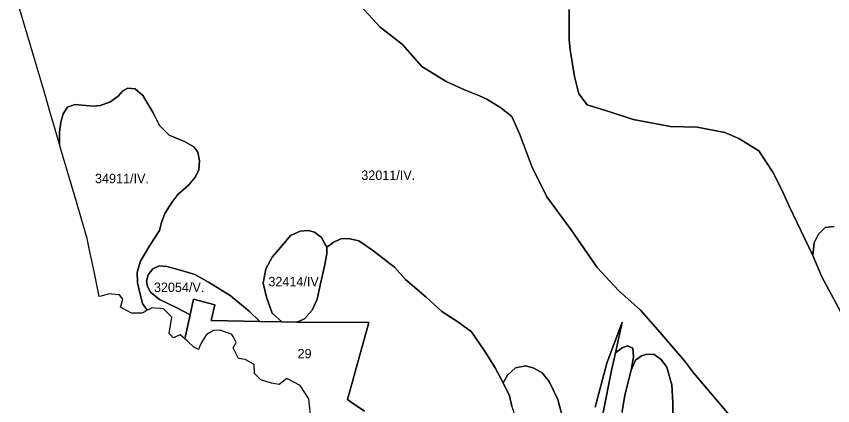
# Model space of a CAD drawing. Extents: x -521621 to -516761, y -1190184 to -1184927.
# Drawn here: x -521384 to -520083, y -1188713 to -1188092 of the extents above; entities that cross this region are included whole.
import ezdxf

# ---------------------------------------------------------------- set-up
doc = ezdxf.new("R2010")
doc.units = 0
doc.layers.add('BPEJ_s', color=7, linetype='Continuous')

msp = doc.modelspace()

# ---------------------------------------------------------------- linework, layer by layer
at = {"layer": 'BPEJ_s'}
for p, q in [((-520502.9, -1188129.6), (-520502.9, -1188081.1)), ((-520501.2, -1188145.7), (-520502.9, -1188129.6)), ((-520494.4, -1188188), (-520501.2, -1188145.7)), ((-520487.6, -1188215.9), (-520494.4, -1188188)), ((-520474, -1188233.3), (-520487.6, -1188215.9)), ((-520437.7, -1188244.7), (-520474, -1188233.3)), ((-520400.7, -1188256.8), (-520437.7, -1188244.7)), ((-520341.1, -1188268.1), (-520400.7, -1188256.8)), ((-520298.8, -1188268.9), (-520341.1, -1188268.1)), ((-520254.9, -1188277.2), (-520298.8, -1188268.9)), ((-520232.3, -1188287), (-520254.9, -1188277.2)), ((-520200.6, -1188306.6), (-520232.3, -1188287)), ((-520177.9, -1188340.7), (-520200.6, -1188306.6)), ((-520163.5, -1188370.1), (-520177.9, -1188340.7)), ((-520152.2, -1188395.1), (-520163.5, -1188370.1)), ((-520114.5, -1188473.7), (-520152.2, -1188395.1)), ((-520094.8, -1188429.1), (-520105.4, -1188439.7)), ((-520080.5, -1188427.6), (-520094.8, -1188429.1)), ((-520105.4, -1188439.7), (-520112.2, -1188453.3)), ((-520112.2, -1188453.3), (-520114.5, -1188473.7))]:
    msp.add_line(p, q, dxfattribs=at)
for points in [[(-520515.5, -1188723.6), (-520520.8, -1188703.3), (-520534.6, -1188674.4), (-520545.6, -1188660.6), (-520559, -1188653.2), (-520572, -1188649.6), (-520588.3, -1188652.8), (-520600.9, -1188664.6), (-520607.8, -1188676.4), (-520620.8, -1188652.8), (-520637.5, -1188625.6), (-520658.6, -1188595.1), (-520680.2, -1188579.6), (-520687.6, -1188574.8), (-520706, -1188563.1), (-520730.7, -1188540.2), (-520763.4, -1188512.1), (-520781.3, -1188492.3), (-520816.1, -1188464.9), (-520837.8, -1188450.3), (-520854.7, -1188446.4), (-520866.8, -1188447.2), (-520879, -1188452.6), (-520889.3, -1188460.5), (-520892.4, -1188454.9), (-520897.7, -1188444.9), (-520908.7, -1188436.4), (-520918.2, -1188433.6), (-520931.8, -1188434.6), (-520946.9, -1188441.8), (-520959.9, -1188457.2), (-520976.3, -1188476.1), (-520986.2, -1188494.7), (-520990.4, -1188517.8), (-520985.3, -1188540.2), (-520976, -1188565.5), (-520960.7, -1188579.6), (-520995.8, -1188578.9), (-521012.8, -1188562.3), (-521043.2, -1188537.6), (-521077.7, -1188516.2), (-521099.2, -1188504), (-521120.9, -1188497.3), (-521144, -1188490.9), (-521156.4, -1188490.2), (-521166.4, -1188495), (-521173.7, -1188504.3), (-521176.3, -1188514.6), (-521174.7, -1188522.9), (-521169.9, -1188532.2), (-521155.5, -1188544), (-521128.3, -1188557.1), (-521106.9, -1188568.1), (-521115.5, -1188606.2), (-521122.8, -1188600.2), (-521130.1, -1188603.1), (-521134.1, -1188604.8), (-521138.4, -1188599.9), (-521140.1, -1188597.9), (-521136, -1188571.9), (-521140.8, -1188567.2), (-521147.2, -1188560.8), (-521149.4, -1188558.5), (-521154.4, -1188558.1), (-521163.3, -1188557.4), (-521168, -1188557), (-521171.5, -1188558.9), (-521175.3, -1188561), (-521182.8, -1188549.9), (-521186.7, -1188535.5), (-521191, -1188517.3), (-521191.5, -1188500), (-521186.2, -1188482.7), (-521170.8, -1188456.7), (-521155.9, -1188433.6), (-521152.6, -1188420.7), (-521147.3, -1188406.7), (-521136.2, -1188388.9), (-521126.6, -1188376.4), (-521108.8, -1188361.1), (-521098.3, -1188348.1), (-521093, -1188337), (-521092, -1188322.6), (-521094.9, -1188308.7), (-521101.2, -1188300.5), (-521116, -1188291.8), (-521123.7, -1188288.5), (-521140.1, -1188281.7), (-521155.9, -1188266.4), (-521166.5, -1188245.2), (-521182.3, -1188218.3), (-521194.8, -1188207.7), (-521206.4, -1188206.8), (-521214, -1188211.1), (-521221.7, -1188219.7), (-521234.7, -1188228.9), (-521250.1, -1188234.2), (-521261.1, -1188235.6), (-521273.1, -1188234.6), (-521290.9, -1188232.7), (-521302.4, -1188237), (-521309.1, -1188247.6), (-521313, -1188261.1), (-521315.4, -1188276.9), (-521314.9, -1188296.7), (-521317.1, -1188289.2), (-521322.5, -1188270.7), (-521329.3, -1188247.6), (-521339.3, -1188213.6), (-521384, -1188061.2)], [(-520247.4, -1188728.4), (-520304.4, -1188660.6), (-520318.7, -1188641.4), (-520361.4, -1188592.2), (-520389, -1188560.5), (-520424, -1188529.5), (-520458.1, -1188492.5), (-520499.7, -1188432.9), (-520538.2, -1188380), (-520562.4, -1188331.6), (-520581.3, -1188280.9), (-520594.1, -1188252.2), (-520611.5, -1188237.9), (-520634.1, -1188224.3), (-520645.5, -1188219.2), (-520669.4, -1188209.2), (-520698.6, -1188195.9), (-520737.7, -1188172), (-520768.2, -1188136.9), (-520804, -1188109.7), (-520834.6, -1188075.8)], [(-520834.6, -1188075.8), (-520804, -1188109.7), (-520768.2, -1188136.9), (-520737.7, -1188172), (-520698.6, -1188195.9), (-520669.4, -1188209.2), (-520645.5, -1188219.2), (-520634.1, -1188224.3), (-520611.5, -1188237.9), (-520594.1, -1188252.2), (-520581.3, -1188280.9), (-520562.4, -1188331.6), (-520538.2, -1188380), (-520499.7, -1188432.9), (-520458.1, -1188492.5), (-520424, -1188529.5), (-520389, -1188560.5), (-520361.4, -1188592.2), (-520318.7, -1188641.4), (-520304.4, -1188660.6), (-520247.4, -1188728.4)], [(-520502.9, -1188081.1), (-520502.9, -1188105), (-520502.9, -1188129.6), (-520501.2, -1188145.7), (-520494.4, -1188188), (-520487.6, -1188215.9), (-520474, -1188233.3), (-520437.7, -1188244.7), (-520400.7, -1188256.8), (-520341.1, -1188268.1), (-520298.8, -1188268.9), (-520254.9, -1188277.2), (-520232.3, -1188287), (-520200.6, -1188306.6), (-520177.9, -1188340.7), (-520163.5, -1188370.1), (-520152.2, -1188395.1), (-520114.5, -1188473.7), (-520100.1, -1188507.7), (-520062.3, -1188578)], [(-520062.3, -1188578), (-520100.1, -1188507.7), (-520114.5, -1188473.7), (-520112.2, -1188453.3), (-520105.4, -1188439.7), (-520094.8, -1188429.1), (-520080.5, -1188427.6)], [(-520829.1, -1188721.8), (-520850.2, -1188707.6), (-520855.9, -1188703.2), (-520822, -1188580.5), (-520936.8, -1188579.8), (-520924.5, -1188574.4), (-520912.6, -1188561), (-520904.3, -1188543.1), (-520899.8, -1188521), (-520892.6, -1188490.7), (-520889.3, -1188470.8), (-520889.3, -1188460.5), (-520879, -1188452.6), (-520866.8, -1188447.2), (-520854.7, -1188446.4), (-520837.8, -1188450.3), (-520816.1, -1188464.9), (-520781.3, -1188492.3), (-520763.4, -1188512.1), (-520730.7, -1188540.2), (-520706, -1188563.1), (-520687.6, -1188574.8), (-520680.2, -1188579.6), (-520658.6, -1188595.1), (-520637.5, -1188625.6), (-520620.8, -1188652.8), (-520607.8, -1188676.4), (-520598, -1188697.6), (-520594, -1188713.9)], [(-520914.1, -1188738.4), (-520917.9, -1188702.1), (-520931.6, -1188681.1), (-520952.7, -1188669.8), (-520964.8, -1188679.1), (-520977.1, -1188677.4), (-520994.2, -1188671.8), (-521004.3, -1188661.6), (-521004.7, -1188647.2), (-521005.8, -1188646.7), (-521017.3, -1188640.4), (-521019.2, -1188639.4), (-521029.7, -1188637.8), (-521038.2, -1188620.9), (-521033.3, -1188612.2), (-521038.5, -1188603), (-521040.5, -1188599.6), (-521044.1, -1188598.2), (-521052.3, -1188595.2), (-521058.9, -1188592.9), (-521068.9, -1188593.3), (-521069.8, -1188593.3), (-521079.9, -1188599), (-521081.1, -1188599.7), (-521089, -1188612.3), (-521091.9, -1188619), (-521093.8, -1188623.6), (-521101.2, -1188619.7), (-521109.9, -1188611), (-521111.5, -1188609.5), (-521115.5, -1188606.2), (-521106.9, -1188568.1), (-521101.3, -1188543.2), (-521067.8, -1188552.5), (-521073.3, -1188577.4), (-520995.8, -1188578.9), (-520960.7, -1188579.6), (-520936.8, -1188579.8), (-520822, -1188580.5), (-520855.9, -1188703.2), (-520850.2, -1188707.6), (-520829.1, -1188721.8)], [(-520461.1, -1188715.4), (-520443, -1188645), (-520418.1, -1188579.7), (-520429.1, -1188628.7), (-520435.4, -1188657), (-520448.5, -1188724)], [(-520338.6, -1188775.3), (-520337.8, -1188707.8), (-520339, -1188679.7), (-520347.1, -1188651.6), (-520356.1, -1188639.4), (-520367.5, -1188631.7), (-520378.8, -1188630.9), (-520387.4, -1188633.7), (-520397.1, -1188640.6), (-520404.1, -1188656.5), (-520400, -1188634.9), (-520401.2, -1188621.1), (-520409.7, -1188617.4), (-520418.3, -1188620.7), (-520429.1, -1188628.7), (-520418.1, -1188579.7), (-520443, -1188645), (-520461.1, -1188715.4)], [(-520418.3, -1188722.4), (-520413.8, -1188696.4), (-520404.1, -1188656.5), (-520397.1, -1188640.6), (-520387.4, -1188633.7), (-520378.8, -1188630.9), (-520367.5, -1188631.7), (-520356.1, -1188639.4), (-520347.1, -1188651.6), (-520339, -1188679.7), (-520337.8, -1188707.8), (-520338.6, -1188775.3)]]:
    msp.add_lwpolyline(points, dxfattribs=at)
for points in [[(-521314.9, -1188296.7), (-521315.4, -1188276.9), (-521313, -1188261.1), (-521309.1, -1188247.6), (-521302.4, -1188237), (-521290.9, -1188232.7), (-521273.1, -1188234.6), (-521261.1, -1188235.6), (-521250.1, -1188234.2), (-521234.7, -1188228.9), (-521221.7, -1188219.7), (-521214, -1188211.1), (-521206.4, -1188206.8), (-521194.8, -1188207.7), (-521182.3, -1188218.3), (-521166.5, -1188245.2), (-521155.9, -1188266.4), (-521140.1, -1188281.7), (-521123.7, -1188288.5), (-521116, -1188291.8), (-521101.2, -1188300.5), (-521094.9, -1188308.7), (-521092, -1188322.6), (-521093, -1188337), (-521098.3, -1188348.1), (-521108.8, -1188361.1), (-521126.6, -1188376.4), (-521136.2, -1188388.9), (-521147.3, -1188406.7), (-521152.6, -1188420.7), (-521155.9, -1188433.6), (-521170.8, -1188456.7), (-521186.2, -1188482.7), (-521191.5, -1188500), (-521191, -1188517.3), (-521186.7, -1188535.5), (-521182.8, -1188549.9), (-521175.3, -1188561), (-521180.4, -1188563.8), (-521183.2, -1188565.3), (-521200.6, -1188565.3), (-521217.9, -1188556.1), (-521217, -1188552.9), (-521214.3, -1188543.2), (-521219.4, -1188536.2), (-521231.5, -1188535.2), (-521234.9, -1188534.9), (-521237.1, -1188535.4), (-521243.5, -1188537), (-521248.9, -1188538.3), (-521251.7, -1188539), (-521260, -1188499.2), (-521267.1, -1188464.9), (-521270.9, -1188446.7), (-521280, -1188415.6), (-521288.1, -1188388.2), (-521311.7, -1188307.7)], [(-520960.7, -1188579.6), (-520976, -1188565.5), (-520985.3, -1188540.2), (-520990.4, -1188517.8), (-520986.2, -1188494.7), (-520976.3, -1188476.1), (-520959.9, -1188457.2), (-520946.9, -1188441.8), (-520931.8, -1188434.6), (-520918.2, -1188433.6), (-520908.7, -1188436.4), (-520897.7, -1188444.9), (-520892.4, -1188454.9), (-520889.3, -1188460.5), (-520889.3, -1188470.8), (-520892.6, -1188490.7), (-520899.8, -1188521), (-520904.3, -1188543.1), (-520912.6, -1188561), (-520924.5, -1188574.4), (-520936.8, -1188579.8)], [(-521106.9, -1188568.1), (-521128.3, -1188557.1), (-521155.5, -1188544), (-521169.9, -1188532.2), (-521174.7, -1188522.9), (-521176.3, -1188514.6), (-521173.7, -1188504.3), (-521166.4, -1188495), (-521156.4, -1188490.2), (-521144, -1188490.9), (-521120.9, -1188497.3), (-521099.2, -1188504), (-521077.7, -1188516.2), (-521043.2, -1188537.6), (-521012.8, -1188562.3), (-520995.8, -1188578.9), (-521073.3, -1188577.4), (-521067.8, -1188552.5), (-521101.3, -1188543.2)], [(-520473.2, -1188838.7), (-520448.5, -1188724), (-520435.4, -1188657), (-520429.1, -1188628.7), (-520418.3, -1188620.7), (-520409.7, -1188617.4), (-520401.2, -1188621.1), (-520400, -1188634.9), (-520404.1, -1188656.5), (-520413.8, -1188696.4), (-520418.3, -1188722.4), (-520427.2, -1188777.8), (-520437.8, -1188827), (-520443.9, -1188856.3), (-520457.3, -1188850.2)], [(-520607.8, -1188676.4), (-520600.9, -1188664.6), (-520588.3, -1188652.8), (-520572, -1188649.6), (-520559, -1188653.2), (-520545.6, -1188660.6), (-520534.6, -1188674.4), (-520520.8, -1188703.3), (-520515.5, -1188723.6), (-520500.8, -1188775.7), (-520487.8, -1188819.7), (-520483.6, -1188836.2), (-520508.2, -1188829), (-520527.2, -1188823.5), (-520552.9, -1188817.6), (-520569.6, -1188812.4), (-520582.6, -1188808.7), (-520588.3, -1188801.4), (-520588.7, -1188789.6), (-520589.5, -1188763.5), (-520589.5, -1188745.6), (-520591.1, -1188722.4), (-520594, -1188713.9), (-520598, -1188697.6)]]:
    msp.add_lwpolyline(points, close=True, dxfattribs=at)

# ---------------------------------------------------------------- texts
for s, p in [('34911/IV.', (-521258.5, -1188358.3)), ('32011/IV.', (-520834.1, -1188353.1)), ('32414/IV.', (-520982.2, -1188522.7)), ('32054/V.', (-521164.6, -1188531.8)), ('29', (-520935.7, -1188637.5))]:
    msp.add_text(s, height=15, dxfattribs=at).set_placement(p)

doc.saveas('drawing.dxf')
